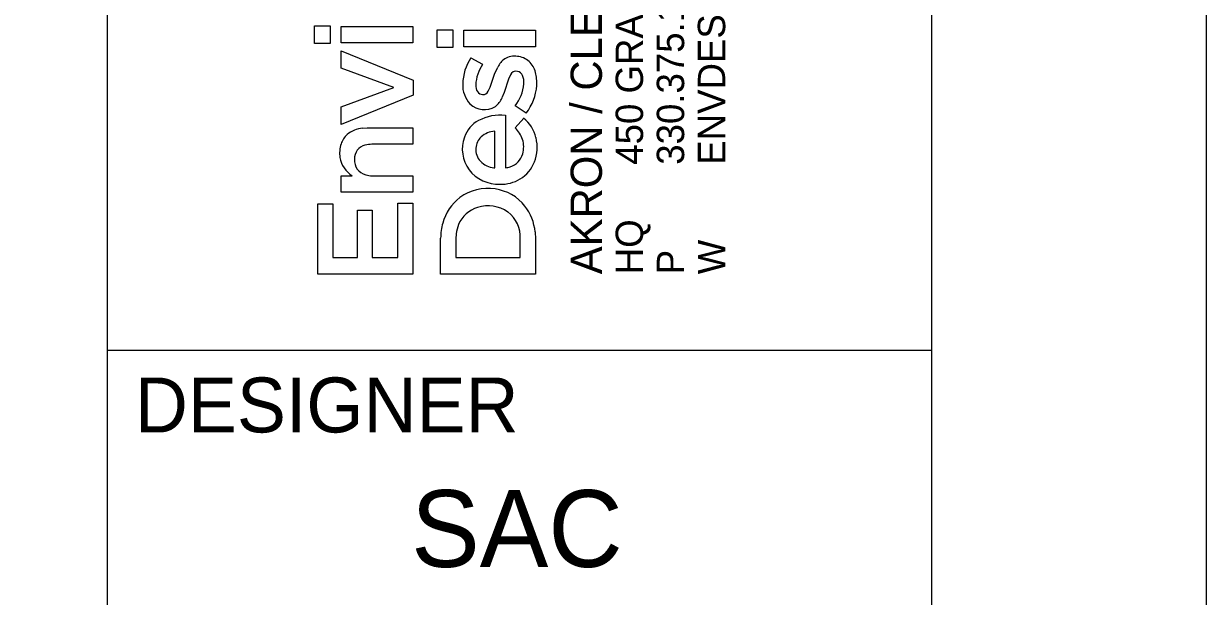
# Model space of a CAD drawing. Extents: x -0.4 to 34, y 0 to 22.
# Drawn here: x 31.848 to 34, y 2.552 to 3.594 of the extents above; entities that cross this region are included whole.
import ezdxf

# ---------------------------------------------------------------- set-up
doc = ezdxf.new("R2010")
doc.units = 0
for name, color, linetype in [('SH_Border', 7, 'Continuous'), ('SH_Cut_Line', 7, 'Continuous'), ('SH_Data', 7, 'Continuous')]:
    doc.layers.add(name, color=color, linetype=linetype)

msp = doc.modelspace()

# ---------------------------------------------------------------- linework, layer by layer
at = {"layer": 'SH_Border'}
for p, q in [((32, 0.5), (32, 21.5)), ((32, 3), (33.5, 3))]:
    msp.add_line(p, q, dxfattribs=at)
msp.add_lwpolyline([(1.5, 21.5), (33.5, 21.5), (33.5, 0.5), (1.5, 0.5)], close=True, dxfattribs=at)
at = {"layer": 'SH_Cut_Line'}
msp.add_lwpolyline([(0, 0), (34, 0), (34, 22), (0, 22)], close=True, dxfattribs=at)
at = {"layer": 'SH_Data'}
for p, q in [((32.3771, 3.5582), (32.3771, 3.5903)), ((32.3771, 3.5903), (32.4054, 3.5903)), ((32.4054, 3.5903), (32.4054, 3.5582)), ((32.4254, 3.5594), (32.4254, 3.5893)), ((32.4254, 3.5893), (32.5557, 3.5893)), ((32.5557, 3.5893), (32.5557, 3.5594)), ((32.6005, 3.5511), (32.6005, 3.5832)), ((32.6005, 3.5832), (32.6289, 3.5832)), ((32.6289, 3.5832), (32.6289, 3.5511)), ((32.6489, 3.5523), (32.6489, 3.5822)), ((32.6489, 3.5822), (32.7792, 3.5822)), ((32.7792, 3.5822), (32.7792, 3.5523)), ((32.4054, 3.5582), (32.3771, 3.5582)), ((32.5557, 3.5594), (32.4254, 3.5594)), ((32.7792, 3.5523), (32.6489, 3.5523)), ((32.4254, 3.5133), (32.4254, 3.5446)), ((32.4254, 3.5446), (32.5567, 3.4913)), ((32.6289, 3.5511), (32.6005, 3.5511)), ((32.6615, 3.5321), (32.6827, 3.5203)), ((32.5212, 3.478), (32.4254, 3.5133)), ((32.7048, 3.5026), (32.7104, 3.5153)), ((32.5567, 3.4913), (32.5567, 3.4644)), ((32.6967, 3.4787), (32.7048, 3.5026)), ((32.7298, 3.4933), (32.7221, 3.4688)), ((32.7334, 3.501), (32.7298, 3.4933)), ((32.4254, 3.4429), (32.5212, 3.478)), ((32.693, 3.4712), (32.6967, 3.4787)), ((32.7221, 3.4688), (32.7182, 3.4592)), ((32.5567, 3.4644), (32.4254, 3.4109)), ((32.7621, 3.4314), (32.742, 3.4447)), ((32.4254, 3.4109), (32.4254, 3.4429)), ((32.7245, 3.4275), (32.7246, 3.3319)), ((32.4644, 3.404), (32.4729, 3.4044)), ((32.4729, 3.4044), (32.5557, 3.4044)), ((32.5557, 3.4044), (32.5557, 3.3746)), ((32.7423, 3.4046), (32.7577, 3.422)), ((32.7049, 3.3318), (32.7049, 3.3983)), ((32.5557, 3.3746), (32.4814, 3.3746)), ((32.4254, 3.2875), (32.4254, 3.3173)), ((32.4254, 3.3173), (32.4455, 3.3173)), ((32.4822, 3.3173), (32.5557, 3.3173)), ((32.5557, 3.3173), (32.5557, 3.2876)), ((32.7036, 3.3317), (32.7049, 3.3318)), ((32.5557, 3.2876), (32.4254, 3.2875)), ((32.383, 3.1379), (32.383, 3.266)), ((32.383, 3.266), (32.4101, 3.266)), ((32.4101, 3.266), (32.4101, 3.1683)), ((32.455, 3.1683), (32.455, 3.2549)), ((32.455, 3.2549), (32.4822, 3.2549)), ((32.4822, 3.2549), (32.4822, 3.1683)), ((32.5286, 3.1683), (32.5286, 3.2672)), ((32.5286, 3.2672), (32.5557, 3.2672)), ((32.5557, 3.2672), (32.5557, 3.1379)), ((32.6347, 3.2118), (32.6341, 3.2023)), ((32.7785, 3.215), (32.7792, 3.2021)), ((32.6064, 3.138), (32.6064, 3.204)), ((32.6341, 3.2023), (32.6341, 3.1684)), ((32.7515, 3.1683), (32.7515, 3.2024)), ((32.7792, 3.2021), (32.7792, 3.138)), ((32.4101, 3.1683), (32.455, 3.1683)), ((32.4822, 3.1683), (32.5286, 3.1683)), ((32.6341, 3.1684), (32.7515, 3.1683)), ((32.5557, 3.1379), (32.383, 3.1379)), ((32.7792, 3.138), (32.6064, 3.138))]:
    msp.add_line(p, q, dxfattribs=at)
for points in [[(32.3771, 3.5582), (32.3771, 3.5903), (32.4054, 3.5903), (32.4054, 3.5582)], [(32.4254, 3.5594), (32.4254, 3.5893), (32.5557, 3.5893), (32.5557, 3.5594)], [(32.6005, 3.5511), (32.6005, 3.5832), (32.6289, 3.5832), (32.6289, 3.5511)], [(32.6489, 3.5523), (32.6489, 3.5822), (32.7792, 3.5822), (32.7792, 3.5523)], [(32.4254, 3.4109), (32.4254, 3.4429), (32.5212, 3.478), (32.4254, 3.5133), (32.4254, 3.5446), (32.5567, 3.4913), (32.5567, 3.4644)], [(32.383, 3.1379), (32.383, 3.266), (32.4101, 3.266), (32.4101, 3.1683), (32.455, 3.1683), (32.455, 3.2549), (32.4822, 3.2549), (32.4822, 3.1683), (32.5286, 3.1683), (32.5286, 3.2672), (32.5557, 3.2672), (32.5557, 3.1379)]]:
    msp.add_lwpolyline(points, close=True, dxfattribs=at)
for points in [[(32.6615, 3.5321), (32.6827, 3.5203)], [(32.693, 3.4712), (32.6967, 3.4787), (32.7048, 3.5026), (32.7104, 3.5153)], [(32.7334, 3.501), (32.7298, 3.4933), (32.7221, 3.4688), (32.7182, 3.4592)], [(32.7621, 3.4314), (32.742, 3.4447)], [(32.7245, 3.4275), (32.7246, 3.3319)], [(32.4644, 3.404), (32.4729, 3.4044), (32.5557, 3.4044), (32.5557, 3.3746), (32.4814, 3.3746)], [(32.7423, 3.4046), (32.7577, 3.422)], [(32.7036, 3.3317), (32.7049, 3.3318), (32.7049, 3.3983)], [(32.4254, 3.2875), (32.4254, 3.3173), (32.4455, 3.3173)], [(32.4822, 3.3173), (32.5557, 3.3173), (32.5557, 3.2876), (32.4254, 3.2875)], [(32.7785, 3.215), (32.7792, 3.2021), (32.7792, 3.138), (32.6064, 3.138)], [(32.6347, 3.2118), (32.6341, 3.2023), (32.6341, 3.1684), (32.7515, 3.1683), (32.7515, 3.2024)], [(32.6064, 3.138), (32.6064, 3.204)]]:
    msp.add_lwpolyline(points, dxfattribs=at)
for centre, radius, start, end in [((32.7364, 3.4826), 0.0897, 146.531, 178.7571), ((32.7364, 3.4826), 0.0897, 146.531, 178.7571), ((32.7466, 3.4971), 0.0405, 125.5118, 153.4159), ((32.7466, 3.4971), 0.0405, 125.5118, 153.4159), ((32.7406, 3.5026), 0.0326, 80.1719, 122.5197), ((32.7406, 3.5026), 0.0326, 80.1719, 122.5197), ((32.7428, 3.4982), 0.0367, 47.7934, 84.6892), ((32.7428, 3.4982), 0.0367, 47.7934, 84.6892), ((32.7452, 3.4789), 0.0749, 146.5112, 176.9101), ((32.7452, 3.4789), 0.0749, 146.5112, 176.9101), ((32.7379, 3.4946), 0.0427, 14.9966, 46.2063), ((32.7379, 3.4946), 0.0427, 14.9966, 46.2063), ((32.7438, 3.4963), 0.0114, 76.6609, 155.7053), ((32.7438, 3.4963), 0.0114, 76.6609, 155.7053), ((32.744, 3.4951), 0.0126, 21.5098, 78.5262), ((32.744, 3.4951), 0.0126, 21.5098, 78.5262), ((32.7259, 3.4877), 0.0321, 354.5726, 22.068), ((32.7259, 3.4877), 0.0321, 354.5726, 22.068), ((32.7104, 3.4867), 0.0712, 355.8306, 15.3914), ((32.7104, 3.4867), 0.0712, 355.8306, 15.3914), ((32.6967, 3.4824), 0.0501, 177.5366, 222.7932), ((32.6967, 3.4824), 0.0501, 177.5366, 222.7932), ((32.6931, 3.4823), 0.0228, 178.4747, 211.0868), ((32.6931, 3.4823), 0.0228, 178.4747, 211.0868), ((32.6833, 3.4767), 0.0115, 212.2368, 268.3777), ((32.6833, 3.4767), 0.0115, 212.2368, 268.3777), ((32.6834, 3.4759), 0.0107, 267.716, 333.7337), ((32.6834, 3.4759), 0.0107, 267.716, 333.7337), ((32.6825, 3.4915), 0.0757, 321.811, 354.7969), ((32.6825, 3.4915), 0.0757, 321.811, 354.7969), ((32.6895, 3.4882), 0.0922, 321.9777, 355.8738), ((32.6895, 3.4882), 0.0922, 321.9777, 355.8738), ((32.686, 3.4753), 0.0375, 225.9854, 302.4797), ((32.686, 3.4753), 0.0375, 225.9854, 302.4797), ((32.681, 3.4758), 0.0408, 308.0877, 335.9874), ((32.681, 3.4758), 0.0408, 308.0877, 335.9874), ((32.7152, 3.3441), 0.0838, 83.615, 118.2876), ((32.7152, 3.3441), 0.0838, 83.615, 118.2876), ((32.4687, 3.3543), 0.0499, 94.9696, 130.2225), ((32.4687, 3.3543), 0.0499, 94.9696, 130.2225), ((32.7024, 3.3691), 0.0558, 118.8308, 160.6244), ((32.7024, 3.3691), 0.0558, 118.8308, 160.6244), ((32.7038, 3.3656), 0.0549, 19.0357, 45.4406), ((32.7038, 3.3656), 0.0549, 19.0357, 45.4406), ((32.7174, 3.3717), 0.0644, 13.5336, 51.3615), ((32.7174, 3.3717), 0.0644, 13.5336, 51.3615), ((32.4635, 3.3626), 0.0402, 132.2219, 161.6818), ((32.4635, 3.3626), 0.0402, 132.2219, 161.6818), ((32.7104, 3.3661), 0.0644, 160.5201, 215.7831), ((32.7104, 3.3661), 0.0644, 160.5201, 215.7831), ((32.7005, 3.3663), 0.0298, 132.9851, 177.179), ((32.7005, 3.3663), 0.0298, 132.9851, 177.179), ((32.7079, 3.3561), 0.0424, 94.008, 130.8817), ((32.7079, 3.3561), 0.0424, 94.008, 130.8817), ((32.7107, 3.3697), 0.047, 344.6059, 17.007), ((32.7107, 3.3697), 0.047, 344.6059, 17.007), ((32.7064, 3.3692), 0.0758, 339.3542, 13.3785), ((32.7064, 3.3692), 0.0758, 339.3542, 13.3785), ((32.4787, 3.3582), 0.056, 162.2736, 187.7919), ((32.4787, 3.3582), 0.056, 162.2736, 187.7919), ((32.4748, 3.3487), 0.025, 103.6865, 182.2187), ((32.4748, 3.3487), 0.025, 103.6865, 182.2187), ((32.4811, 3.3286), 0.046, 89.6049, 105.3284), ((32.4811, 3.3286), 0.046, 89.6049, 105.3284), ((32.7017, 3.365), 0.0311, 175.0013, 223.283), ((32.7017, 3.365), 0.0311, 175.0013, 223.283), ((32.4703, 3.358), 0.0476, 188.962, 238.7037), ((32.4703, 3.358), 0.0476, 188.962, 238.7037), ((32.4773, 3.3456), 0.0276, 175.5854, 255.1439), ((32.4773, 3.3456), 0.0276, 175.5854, 255.1439), ((32.7089, 3.3736), 0.0423, 225.0619, 262.7974), ((32.7089, 3.3736), 0.0423, 225.0619, 262.7974), ((32.7224, 3.3671), 0.035, 288.0077, 343.5508), ((32.7224, 3.3671), 0.035, 288.0077, 343.5508), ((32.7189, 3.3652), 0.0626, 300.9427, 338.7323), ((32.7189, 3.3652), 0.0626, 300.9427, 338.7323), ((32.4818, 3.3595), 0.0422, 254.0916, 270.5284), ((32.4818, 3.3595), 0.0422, 254.0916, 270.5284), ((32.7125, 3.3705), 0.0687, 217.7452, 271.6543), ((32.7125, 3.3705), 0.0687, 217.7452, 271.6543), ((32.7247, 3.3522), 0.0202, 269.7003, 294.8711), ((32.7247, 3.3522), 0.0202, 269.7003, 294.8711), ((32.6923, 3.2079), 0.0864, 81.194, 125.9984), ((32.6923, 3.2079), 0.0864, 81.194, 125.9984), ((32.6946, 3.2113), 0.0827, 37.8521, 82.402), ((32.6946, 3.2113), 0.0827, 37.8521, 82.402), ((32.7155, 3.3724), 0.0706, 269.2048, 300.3341), ((32.7155, 3.3724), 0.0706, 269.2048, 300.3341), ((32.6939, 3.2089), 0.0865, 127.2362, 165.148), ((32.6939, 3.2089), 0.0865, 127.2362, 165.148), ((32.6889, 3.2078), 0.054, 106.1881, 157.3861), ((32.6889, 3.2078), 0.054, 106.1881, 157.3861), ((32.6928, 3.1986), 0.0639, 55.6727, 107.2093), ((32.6928, 3.1986), 0.0639, 55.6727, 107.2093), ((32.6929, 3.205), 0.0587, 357.4662, 52.2665), ((32.6929, 3.205), 0.0587, 357.4662, 52.2665), ((32.6859, 3.2057), 0.0931, 5.7333, 37.304), ((32.6859, 3.2057), 0.0931, 5.7333, 37.304), ((32.7143, 3.2028), 0.1078, 164.7861, 179.3704), ((32.7143, 3.2028), 0.1078, 164.7861, 179.3704), ((32.6983, 3.2039), 0.0641, 157.3571, 172.9275), ((32.6983, 3.2039), 0.0641, 157.3571, 172.9275)]:
    msp.add_arc(centre, radius, start, end, dxfattribs=at)

# ---------------------------------------------------------------- texts
for s, height, p in [('450 GRANT ST., AKRON, OH  44311', 0.049846, (32.9749, 3.3374)), ('AKRON / CLEVELAND / COLUMBUS', 0.056969, (32.9001, 3.138)), ('ENVDESIGNGROUP.COM', 0.049846, (33.1244, 3.3374)), ('330.375.1390', 0.049846, (33.0497, 3.3374)), ('HQ ', 0.04985, (32.9749, 3.138)), ('W', 0.0498, (33.1244, 3.138)), ('P', 0.0498, (33.0497, 3.138))]:
    msp.add_text(s, height=height, rotation=90, dxfattribs=at).set_placement(p)
for s, height, p in [('DESIGNER', 0.1, (32.05, 2.85)), ('SAC', 0.14, (32.5528, 2.605))]:
    msp.add_text(s, height=height, dxfattribs=at).set_placement(p)

doc.saveas('drawing.dxf')
